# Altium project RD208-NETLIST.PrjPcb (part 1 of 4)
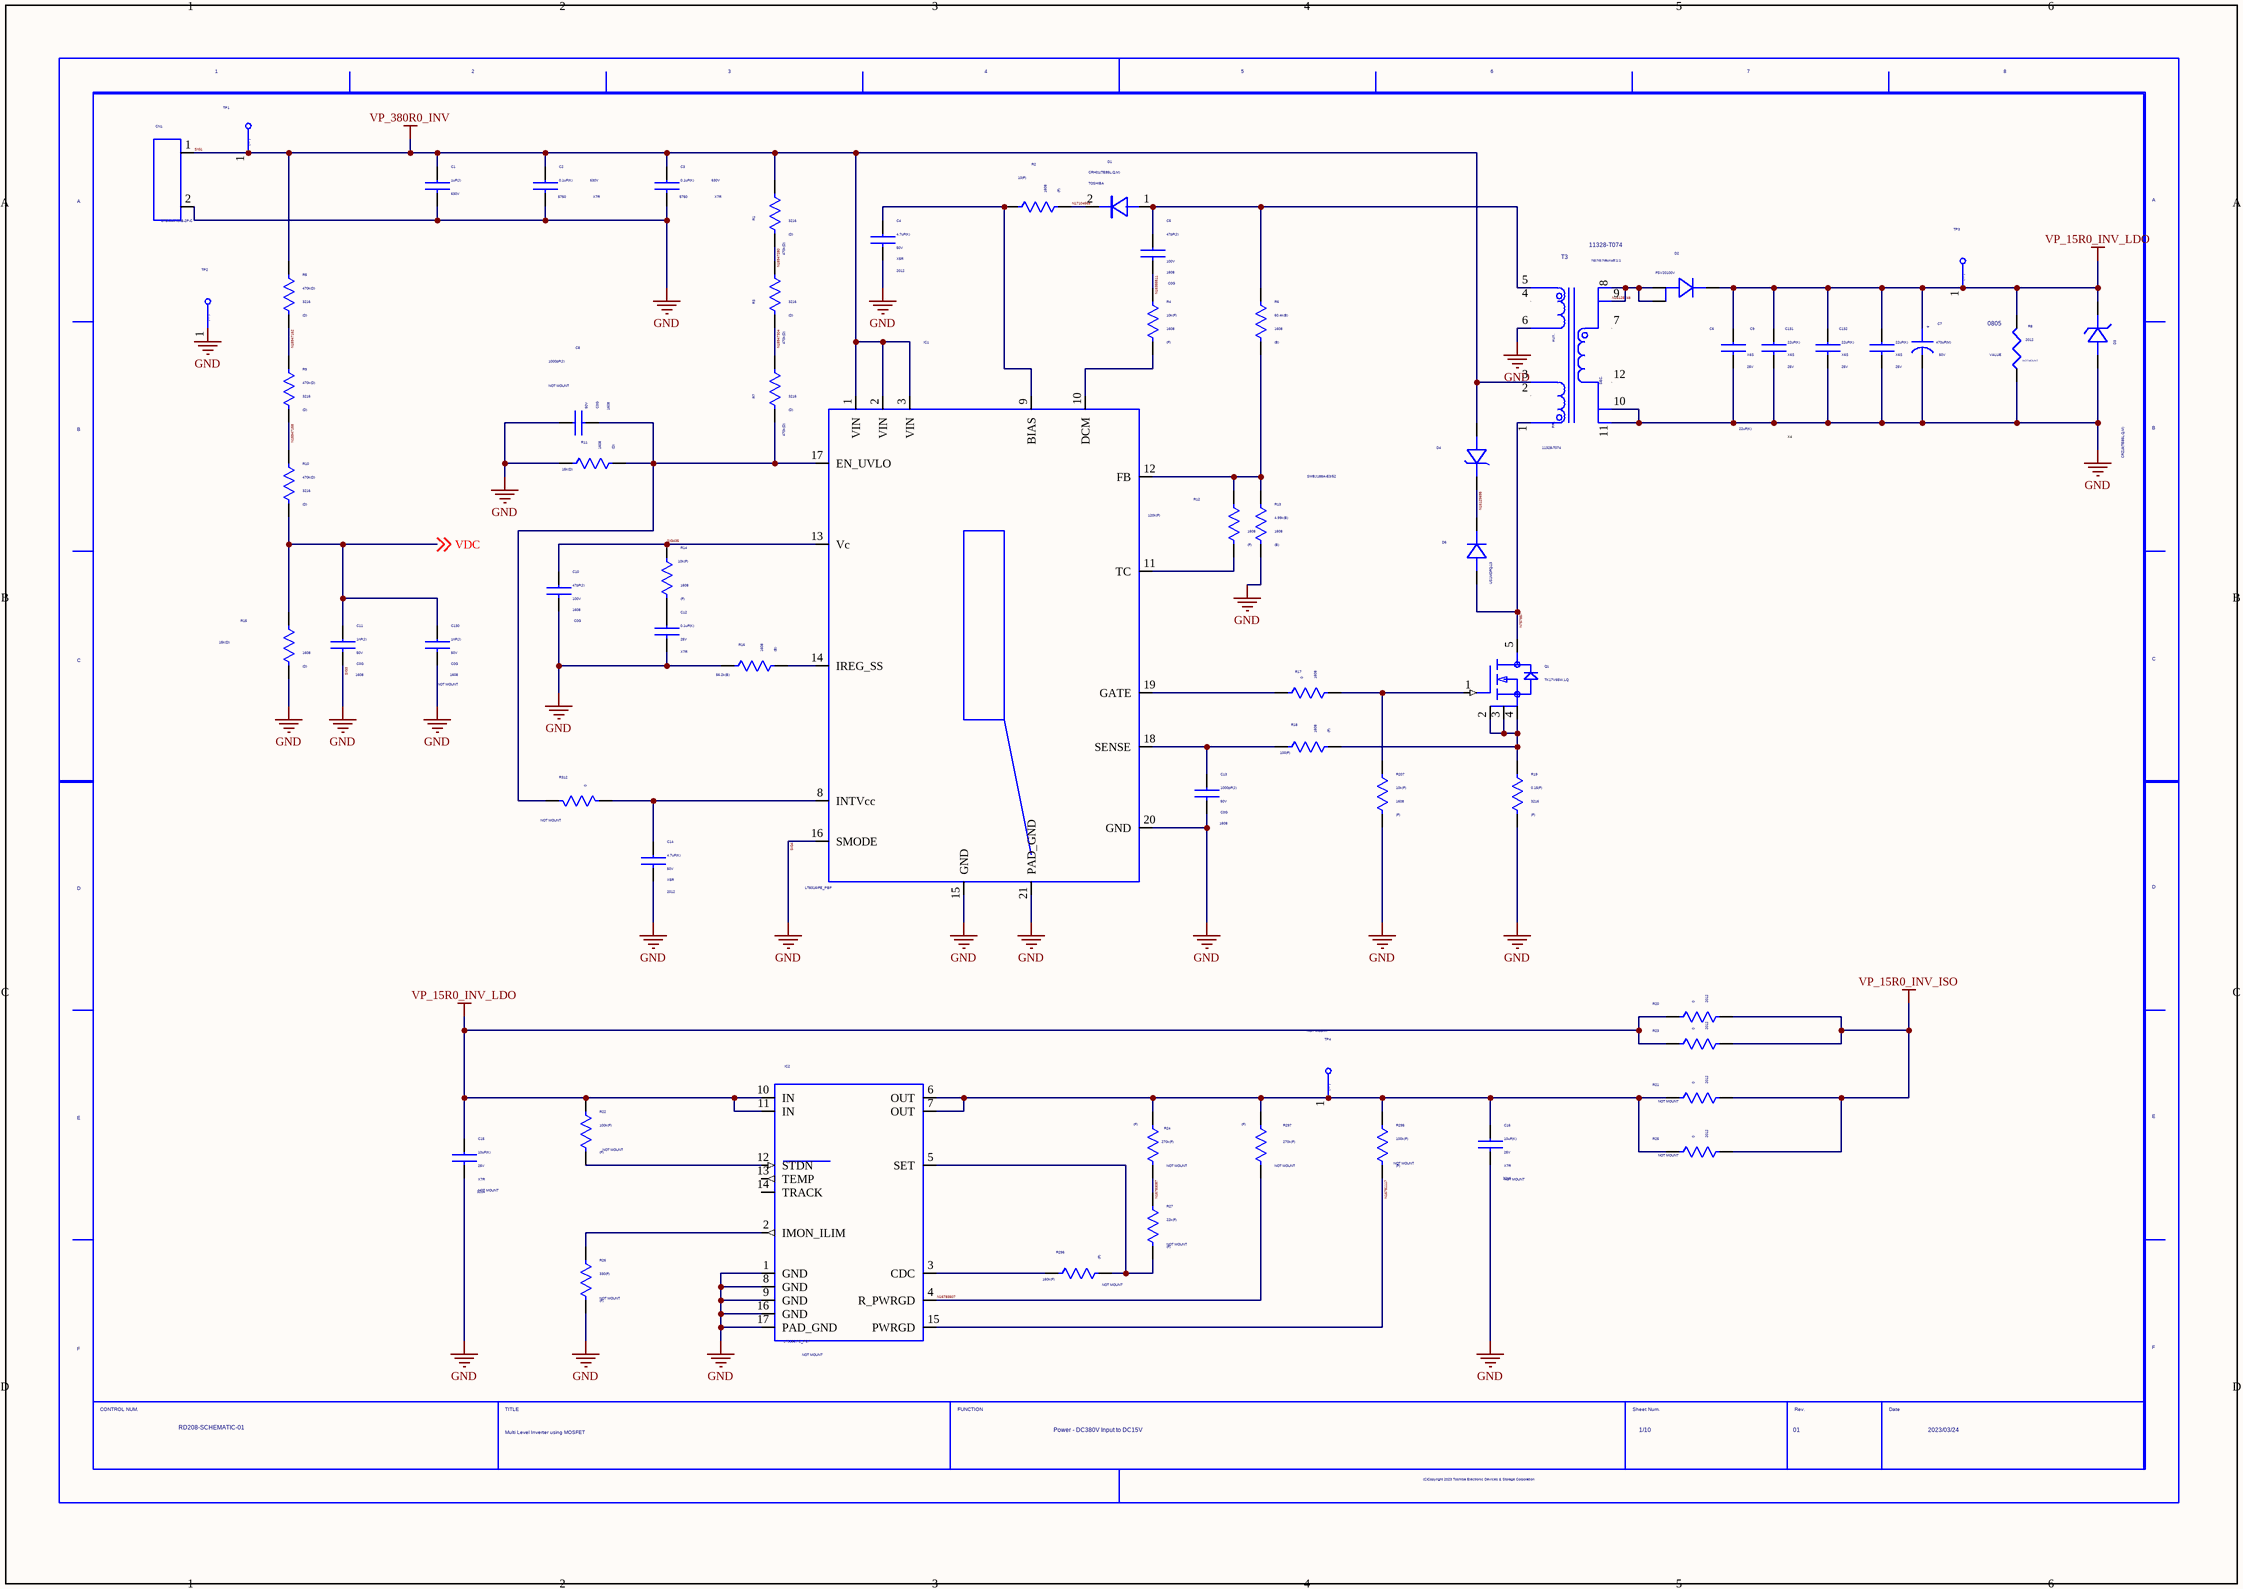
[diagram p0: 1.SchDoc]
10 sheets, 782 parts. Net scope: global (net labels, ports and power ports of the same name join across sheets).
Sheets:
  1.SchDoc
  2.SchDoc
  3.SchDoc
  4.SchDoc
  5.SchDoc
  6.SchDoc
  7.SchDoc
  8.SchDoc
  9.SchDoc
  10.SchDoc

## Sheet 1.SchDoc
size 420 x 297 mm

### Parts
(Parts that share a designator on the sheet are numbered #1, #2 ... from top to bottom, then left to right.)
C1  VAL2: 630V  VAL1: 1uF(J)  (hidden comment: ECWFG2J105P1)
C2  VAL2: 630V  SIZECODESMD: 5750  VALUE4: X7R  VAL1: 0.1uF(K)  (hidden comment: 2220CC104KAT1A)
C3  VAL2: 630V  SIZECODESMD: 5750  VALUE4: X7R  VAL1: 0.1uF(K)  (hidden comment: 2220CC104KAT1A)
C4  VAL2: 50V  SIZECODESMD: 2012  VALUE4: X5R  VAL1: 4.7uF(K)  (hidden comment: GRM21BR61H475KE51L)
C5  VAL2: 100V  SIZECODESMD: 1608  VALUE4: C0G  VAL1: 47pF(J)  (hidden comment: GRM1885C2A470JA01D)
C6  VAL2: 25V  VALUE4: X6S  VAL1: 22uF(K)  (hidden comment: GRM31CC81E226KE11L)
C7  VAL2: 50V  VAL1: 470uF(M)  (hidden comment: EKY_500ELL471ML15S)
C8  VAL2: 50V  SIZECODESMD: 1608  VALUE4: C0G  VAL1: 1000pF(J)  NOTMOUNT: NOT MOUNT  (hidden comment: GRM1885C1H102JA01J)
C9  VAL2: 25V  VALUE4: X6S  VAL1: 22uF(K)  (hidden comment: GRM31CC81E226KE11L)
C10  VAL2: 100V  SIZECODESMD: 1608  VALUE4: C0G  VAL1: 47pF(J)  (hidden comment: GRM1885C2A470JA01D)
C11  VAL2: 50V  SIZECODESMD: 1608  VALUE4: C0G  VAL1: 1nF(J)  (hidden comment: GRM1885C1H102JA01J)
C12  VAL2: 25V  VALUE4: X7R  VAL1: 0.1uF(K)  (hidden comment: GRM155R71E104KE14D)
C13  VAL2: 50V  SIZECODESMD: 1608  VALUE4: C0G  VAL1: 1000pF(J)  (hidden comment: GRM1885C1H102JA01J)
C14  VAL2: 50V  SIZECODESMD: 2012  VALUE4: X5R  VAL1: 4.7uF(K)  (hidden comment: GRM21BR61H475KE51L)
C15  VAL2: 25V  SIZECODESMD: 3216  VALUE4: X7R  VAL1: 10uF(K)  NOTMOUNT: NOT MOUNT  (hidden comment: GRM31CR71E106MA12K)
C16  VAL2: 25V  SIZECODESMD: 3216  VALUE4: X7R  VAL1: 10uF(K)  NOTMOUNT: NOT MOUNT  (hidden comment: GRM31CR71E106MA12K)
C130  VAL2: 50V  SIZECODESMD: 1608  VALUE4: C0G  VAL1: 1nF(J)  NOTMOUNT: NOT MOUNT  (hidden comment: GRM1885C1H102JA01J)
C131  VAL2: 25V  VALUE4: X6S  VAL1: 22uF(K)  (hidden comment: GRM31CC81E226KE11L)
C132  VAL2: 25V  VALUE4: X6S  VAL1: 22uF(K)  (hidden comment: GRM31CC81E226KE11L)
CN1  VAL1: OTB-640NS-B-2P-C  (hidden comment: OTB_640NS_B_2P_C)
D1  USERCOMPTEXT3: TOSHIBA  VAL3: CRH01(TE85L,Q,M)  (hidden comment: CRH01_TE85L,Q,M_)
D2  FSV20100V  [SOD-323]
D3  VAL3: CRZ18(TE85L,Q,M)  (hidden comment: CRZ18_TE85L,Q,M_)
D4  VAL1: SMBJ188A-E3/52  (hidden comment: SMBJ188A_E3_52)
D6  VAL1: US1MDFQ-13  (hidden comment: US1MDFQ_13)
IC1  LT8316IFE_PBF
IC2  NOTMOUNT: NOT MOUNT  (hidden comment: LT3086IFE_PBF)
Q1  TK17V65W,LQ
R1  SIZECODESMD: 3216  VALUE4: (D)  VAL1: 470k(D)  (hidden comment: HV73V2BTTD4703D)
R2  SIZECODESMD: 1608  VALUE4: (F)  VAL1: 10(F)  (hidden comment: ERJ3EKF10R0V)
R3  SIZECODESMD: 3216  VALUE4: (D)  VAL1: 470k(D)  (hidden comment: HV73V2BTTD4703D)
R4  SIZECODESMD: 1608  VALUE4: (F)  VAL1: 10k(F)  (hidden comment: ERJ3EKF1002V)
R5  SIZECODESMD: 3216  VALUE4: (D)  VAL1: 470k(D)  (hidden comment: HV73V2BTTD4703D)
R6  SIZECODESMD: 1608  VAL1: 60.4k(B)  VLUE4: (B)  (hidden comment: ERA3APB6042V)
R7  SIZECODESMD: 3216  VALUE4: (D)  VAL1: 470k(D)  (hidden comment: HV73V2BTTD4703D)
R8  SIZE: 0805  VAL1: VALUE  SIZECODESMD: 2012  NOTMOUNT: NOT MOUNT  [3216]  (hidden comment: AAC_0805)
R9  SIZECODESMD: 3216  VALUE4: (D)  VAL1: 470k(D)  (hidden comment: HV73V2BTTD4703D)
R10  SIZECODESMD: 3216  VALUE4: (D)  VAL1: 470k(D)  (hidden comment: HV73V2BTTD4703D)
R11  SIZECODESMD: 1608  VALUE4: (D)  VAL1: 15k(D)  (hidden comment: RK73H1JRTTD1502D)
R12  SIZECODESMD: 1608  VALUE4: (F)  VAL1: 120k(F)  (hidden comment: ERJ3EKF1203V)
R13  SIZECODESMD: 1608  VALUE4: (B)  VAL1: 4.99k(B)  (hidden comment: ERA3AEB4991V)
R14  SIZECODESMD: 1608  VALUE4: (F)  VAL1: 10k(F)  (hidden comment: ERJ3EKF1002V)
R15  SIZECODESMD: 1608  VALUE4: (D)  VAL1: 15k(D)  (hidden comment: RK73H1JRTTD1502D)
R16  SIZECODESMD: 1608  VALUE4: (B)  VAL1: 56.2k(B)  (hidden comment: ERA3ARB5622V)
R17  SIZECODESMD: 1608  VAL1: 0  (hidden comment: ERJ3GEY0R00V)
R18  SIZECODESMD: 1608  VALUE4: (F)  VAL1: 100(F)  (hidden comment: ERJ3EKF1000V)
R19  SIZECODESMD: 3216  VALUE4: (F)  VAL1: 0.15(F)  (hidden comment: KRL1632E_M_R150_F_T5)
R20  SIZECODESMD: 2012  VAL1: 0  (hidden comment: ERJ6GEY0R00V)
R21  SIZECODESMD: 2012  VAL1: 0  NOTMOUNT: NOT MOUNT  (hidden comment: ERJ6GEY0R00V)
R22  VALUE4: (F)  VAL1: 100k(F)  NOTMOUNT: NOT MOUNT  (hidden comment: ERJ2RKF1003X)
R23  SIZECODESMD: 2012  VAL1: 0  (hidden comment: ERJ6GEY0R00V)
R24  VALUE4: (F)  VAL1: 270k(F)  NOTMOUNT: NOT MOUNT  (hidden comment: ERJ2RKF2703X)
R25  SIZECODESMD: 2012  VAL1: 0  NOTMOUNT: NOT MOUNT  (hidden comment: ERJ6GEY0R00V)
R26  VALUE4: (F)  VAL1: 330(F)  NOTMOUNT: NOT MOUNT  (hidden comment: ERJ2RKF3300X)
R27  VALUE4: (F)  VAL1: 22k(F)  NOTMOUNT: NOT MOUNT  (hidden comment: ERJ2RKF2202X)
R207  SIZECODESMD: 1608  VALUE4: (F)  VAL1: 10k(F)  (hidden comment: ERJ3EKF1002V)
R295  VALUE4: (F)  VAL1: 100k(F)  NOTMOUNT: NOT MOUNT  (hidden comment: ERJ2RKF1003X)
R296  VALUE4: (F)  VAL1: 160k(F)  NOTMOUNT: NOT MOUNT  (hidden comment: ERJ2RKF1603X)
R297  VALUE4: (F)  VAL1: 270k(F)  NOTMOUNT: NOT MOUNT  (hidden comment: ERJ2RKF2703X)
R312  VAL1: 0  NOTMOUNT: NOT MOUNT  (hidden comment: ERJ2GE0R00X)
T3  VAL2: Np:Ns:Naux=8:1:1  VAL1: 11328-T074  (hidden comment: 11328_T074)
TP1  TP  (value not drawn)
TP2  TP  (value not drawn)
TP3  TP  (value not drawn)
TP4  NOTMOUNT: NOT MOUNT  (hidden comment: TP)
U?#1  DATE: 2023/03/24  TITLE: Multi Level Inverter using MOSFET  DRAWINGNUMBER: RD208-SCHEMATIC-01  REVISION: 01  SHEETNUMBER: 1/10  FUNCTION: Power - DC380V Input to DC15V  (hidden comment: WAKU_DEF100)

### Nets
GND: C1.2 C2.2 C3.2 C4.2 C6.2 C7.2 C8.1 C9.2 C10.2 C11.2 C12.2 C13.2 C14.2 C15.2 C16.2 C130.2 C131.2 C132.2 CN1.2 D3.A(ANODE) IC1.15(GND) IC1.16(SMODE) IC1.20(GND) IC1.21(PAD_GND) IC2.1(GND) IC2.8(GND) IC2.9(GND) IC2.16(GND) IC2.17(PAD_GND) R8.1 R11.1 R13.2 R15.2 R16.1 R19.2 R26.2 R207.2 T3.6 T3.10 T3.11 TP2.1  [also labelled SIG3, SIG4]  [project net SIG200]
SIG1: C1.1 C2.1 C3.1 CN1.1 D4.A(ANODE) IC1.1(VIN) IC1.2(VIN) IC1.3(VIN) R1.1 R5.1 T3.3 TP1.1  [also labelled VP_380R0_INV]
VP_15R0_INV_ISO: R20.2 R21.2 R23.2 R25.2
VP_15R0_INV_LDO: C6.1 C7.1 C9.1 C15.1 C131.1 C132.1 D2.3(CATHODE) D3.K(CATHODE) IC2.10(IN) IC2.11(IN) R8.2 R20.1 R22.1 R23.1 TP3.1
LDO_15V_CDC: IC2.3(CDC) R296.1
LDO_15V_ILIM: IC2.2(IMON_ILIM) R26.1
LDO_15V_SET: IC2.5(SET) R27.2 R296.2
LDO_15V_STD_N: IC2.12(STDN) R22.2
LDO_15VOUT: C16.1 IC2.6(OUT) IC2.7(OUT) R21.1 R24.2 R25.1 R295.1 R297.2 TP4.1
LT8316_BIAS: C4.1 IC1.9(BIAS) R2.1
LT8316_DCM: IC1.10(DCM) R4.2
LT8316_EN: C8.2 IC1.17(EN_UVLO) R7.2 R11.2 R312.2
LT8316_FB: IC1.12(FB) R6.2 R12.1 R13.1
LT8316_FB_B: C5.1 D1.1(A) R6.1 T3.5
LT8316_GATE: IC1.19(GATE) R17.1
LT8316_GATE_B: Q1.1(G) R17.2 R207.1
LT8316_INTVCC: C14.1 IC1.8(INTVcc) R312.1
LT8316_IREG: IC1.14(IREG_SS) R16.2
LT8316_SENSE: C13.1 IC1.18(SENSE) R18.1
LT8316_SENSE_B: Q1.2(S2) Q1.3(S3) Q1.4(S4) R18.2 R19.1
LT8316_TC: IC1.11(TC) R12.2
N757857: D6.A(ANODE) Q1.5(D) T3.1
N15947158: R9.2 R10.1
N15947162: R5.2 R9.1
N15947280: R1.2 R3.1
N15947304: R3.2 R7.1
N16128748: D2.1(ANODE-1) D2.2(ANODE-2) T3.8 T3.9
N16129695: D4.K(CATHODE) D6.K(CATHODE)
N16355511: C5.2 R4.1
N16781117: IC2.15(PWRGD) R295.2
N16783087: R24.1 R27.1
N16783507: IC2.4(R_PWRGD) R297.1
N17104568: D1.2(C) R2.2
SIG435: C10.1 IC1.13(Vc) R14.1
VDC: C11.1 C130.1 R10.2 R15.1 ; off-sheet VDC
NetC12_1: C12.1 R14.2

Not connected (* = marked no-connect by the designer): IC2 13(TEMP) 14(TRACK); T3 2 4 7 12

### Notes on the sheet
- X4

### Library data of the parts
C1 = ECWFG2J105P1: MANUFACTURER: PANASONIC; ITEM: CAP Film; TIME: 08:44:47; UPDATEUSER: t5459927; SAVECOUNT: 1; OriginalSymbolOrigin: (0,0); INSTANCENAME: INS15925304
C2 = 2220CC104KAT1A: MANUFACTURER: AVX; ITEM: CAP Ceramic; TIME: 08:44:47; UPDATEUSER: t5459927; SAVECOUNT: 1; OriginalSymbolOrigin: (0,0); INSTANCENAME: INS16805650
C3 = 2220CC104KAT1A: MANUFACTURER: AVX; ITEM: CAP Ceramic; TIME: 08:44:47; UPDATEUSER: t5459927; SAVECOUNT: 1; OriginalSymbolOrigin: (0,0); INSTANCENAME: INS16806135
C4 = GRM21BR61H475KE51L: MANUFACTURER: MURATA; ITEM: CAP Ceramic; TIME: 08:44:46; UPDATEUSER: t5459927; SAVECOUNT: 1; OriginalSymbolOrigin: (0,0); INSTANCENAME: INS15926838
C5 = GRM1885C2A470JA01D: MANUFACTURER: MURATA; ITEM: CAP Ceramic; TIME: 08:44:47; UPDATEUSER: t5459927; SAVECOUNT: 1; OriginalSymbolOrigin: (0,0); INSTANCENAME: INS15927173
C6 = GRM31CC81E226KE11L: MANUFACTURER: MURATA; ITEM: CAP Ceramic; SIZECODESMD: 3216; TIME: 08:44:47; UPDATEUSER: t5459927; SAVECOUNT: 1; OriginalSymbolOrigin: (0,0); INSTANCENAME: INS16787498
C7 = EKY_500ELL471ML15S: MANUFACTURER: Nippon Chemi-Con; ITEM: CAP ALUM; SIZECODESMD: 16.0mm; COMP: EKY-500ELL471ML15S; TIME: 08:44:47; UPDATEUSER: t5459927; SAVECOUNT: 1; OriginalSymbolOrigin: (0,2540); INSTANCENAME: INS15936364
C8 = GRM1885C1H102JA01J: MANUFACTURER: MURATA; ITEM: CAP Ceramic; TIME: 08:44:47; UPDATEUSER: t5459927; SAVECOUNT: 1; OriginalSymbolOrigin: (0,0); INSTANCENAME: INS16256315
C9 = GRM31CC81E226KE11L: MANUFACTURER: MURATA; ITEM: CAP Ceramic; SIZECODESMD: 3216; TIME: 08:44:47; UPDATEUSER: t5459927; SAVECOUNT: 1; OriginalSymbolOrigin: (0,0); INSTANCENAME: INS16787510
C10 = GRM1885C2A470JA01D: MANUFACTURER: MURATA; ITEM: CAP Ceramic; TIME: 08:44:47; UPDATEUSER: t5459927; SAVECOUNT: 1; OriginalSymbolOrigin: (0,0); INSTANCENAME: INS15928528
C11 = GRM1885C1H102JA01J: MANUFACTURER: MURATA; ITEM: CAP Ceramic; TIME: 08:44:47; UPDATEUSER: t5459927; SAVECOUNT: 1; OriginalSymbolOrigin: (0,0); INSTANCENAME: INS16143125
C12 = GRM155R71E104KE14D: MANUFACTURER: MURATA; ITEM: CAP Ceramic; SIZECODESMD: 1005; TIME: 08:44:45; UPDATEUSER: t5459927; SAVECOUNT: 1; OriginalSymbolOrigin: (0,0); INSTANCENAME: INS15928810
C13 = GRM1885C1H102JA01J: MANUFACTURER: MURATA; ITEM: CAP Ceramic; TIME: 08:44:47; UPDATEUSER: t5459927; SAVECOUNT: 1; OriginalSymbolOrigin: (0,0); INSTANCENAME: INS15928036
C14 = GRM21BR61H475KE51L: MANUFACTURER: MURATA; ITEM: CAP Ceramic; TIME: 08:44:46; UPDATEUSER: t5459927; SAVECOUNT: 1; OriginalSymbolOrigin: (0,0); INSTANCENAME: INS15928288
C15 = GRM31CR71E106MA12K: MANUFACTURER: MURATA; ITEM: CAP Ceramic; TIME: 08:44:46; UPDATEUSER: t5459927; SAVECOUNT: 1; OriginalSymbolOrigin: (0,0); INSTANCENAME: INS3166104
C16 = GRM31CR71E106MA12K: MANUFACTURER: MURATA; ITEM: CAP Ceramic; TIME: 08:44:46; UPDATEUSER: t5459927; SAVECOUNT: 1; OriginalSymbolOrigin: (0,0); INSTANCENAME: INS3166501
C130 = GRM1885C1H102JA01J: MANUFACTURER: MURATA; ITEM: CAP Ceramic; TIME: 08:44:47; UPDATEUSER: t5459927; SAVECOUNT: 1; OriginalSymbolOrigin: (0,0); INSTANCENAME: INS16143791
C131 = GRM31CC81E226KE11L: MANUFACTURER: MURATA; ITEM: CAP Ceramic; SIZECODESMD: 3216; TIME: 08:44:47; UPDATEUSER: t5459927; SAVECOUNT: 1; OriginalSymbolOrigin: (0,0); INSTANCENAME: INS16787460
C132 = GRM31CC81E226KE11L: MANUFACTURER: MURATA; ITEM: CAP Ceramic; SIZECODESMD: 3216; TIME: 08:44:47; UPDATEUSER: t5459927; SAVECOUNT: 1; OriginalSymbolOrigin: (0,0); INSTANCENAME: INS16787472
CN1 = OTB_640NS_B_2P_C: MANUFACTURER: OSADA; ITEM: Connector; VAL2: 11mm   x2; TIME: 08:44:47; UPDATEUSER: t5459927; SAVECOUNT: 1; SAVEAREA0: -10166,-15544,12232,852; OriginalSymbolOrigin: (0,0); INSTANCENAME: INS17151887
D1 = CRH01_TE85L,Q,M_: 5TH PART FIELD: CRH01; ITEM: DIODE; COMP: CRH01-12; TIME: 08:44:47; UPDATEUSER: t5459927; SAVECOUNT: 1; OriginalSymbolOrigin: (0,0); INSTANCENAME: INS760252
D2 = FSV20100V: MANUFACTURER: On semiconductor; COMP: FSV20100V-123; ITEM: DIODE; TIME: 08:44:47; UPDATEUSER: t5459927; SAVECOUNT: 1; OriginalSymbolOrigin: (0,2540); INSTANCENAME: INS15937116
D3 = CRZ18_TE85L,Q,M_: MANUFACTURER: TOSHIBA; COMP: CRZ18; ITEM: DIODE Zener; TIME: 08:44:47; UPDATEUSER: t5459927; SAVECOUNT: 1; OriginalSymbolOrigin: (0,0); INSTANCENAME: INS16129113
D4 = SMBJ188A_E3_52: MANUFACTURER: Vishay; COMP: SMBJ188A-E3_52; ITEM: DIODE TVS; TIME: 08:44:47; UPDATEUSER: t5459927; SAVECOUNT: 1; OriginalSymbolOrigin: (0,0); INSTANCENAME: INS15937273
D6 = US1MDFQ_13: MANUFACTURER: DIODES; ITEM: DIODE; VAL2: 1000V; SIZECODESMD: 1A; TIME: 08:44:47; UPDATEUSER: t5459927; SAVECOUNT: 1; OriginalSymbolOrigin: (0,0); INSTANCENAME: INS16150519
IC1 = LT8316IFE_PBF: MANUFACTURER: Analog Devices; ITEM: IC DCDC; TIME: 08:44:47; UPDATEUSER: PS4_common_PC; UPDATETIME: 14:20:20; SAVECOUNT: 5; SAVEAREA0: -89670,-104109,148818,4559; OriginalSymbolOrigin: (0,0); COMP: LT-20-Lead-Plastic-TSSOP-FE-R-SP-17p
IC2 = LT3086IFE_PBF: MANUFACTURER: Analog Devices; ITEM: LDO; TIME: 08:44:47; UPDATEUSER: PS4_common_PC; UPDATETIME: 14:21:05; SAVECOUNT: 5; SAVEAREA0: -46534,-51518,75335,4012; OriginalSymbolOrigin: (0,0)
Q1 = TK17V65W,LQ: MANUFATURER: TOSHIBA; ITEM: FET; TIME: 08:44:45; UPDATEUSER: t5459927; SAVECOUNT: 1; OriginalSymbolOrigin: (0,0); INSTANCENAME: INS15937568
R1 = HV73V2BTTD4703D: MANUFACTURER: KOA; ITEM: Register; VAL2: 0.33W; TIME: 08:44:45; UPDATEUSER: t5459927; SAVECOUNT: 1; OriginalSymbolOrigin: (0,0); INSTANCENAME: INS16809998
R2 = ERJ3EKF10R0V: MANUFACTURER: Panasonic; ITEM: Register; VAL2: 100mW; TIME: 08:44:45; UPDATEUSER: t5459927; SAVECOUNT: 1; OriginalSymbolOrigin: (0,0); INSTANCENAME: INS17104536
R3 = HV73V2BTTD4703D: MANUFACTURER: KOA; ITEM: Register; VAL2: 0.33W; TIME: 08:44:45; UPDATEUSER: t5459927; SAVECOUNT: 1; OriginalSymbolOrigin: (0,0); INSTANCENAME: INS16810014
R4 = ERJ3EKF1002V: MANUFACTURER: Panasonic; ITEM: Register; VAL2: 100mW; TIME: 08:44:46; UPDATEUSER: t5459927; SAVECOUNT: 1; OriginalSymbolOrigin: (0,0); INSTANCENAME: INS15927083
R5 = HV73V2BTTD4703D: MANUFACTURER: KOA; ITEM: Register; VAL2: 0.33W; TIME: 08:44:45; UPDATEUSER: t5459927; SAVECOUNT: 1; OriginalSymbolOrigin: (0,0); INSTANCENAME: INS16806683
R6 = ERA3APB6042V: MANUFACTURER: Panasonic; ITEM: Register; VAL2: 100mW; TIME: 08:44:47; UPDATEUSER: t5459927; SAVECOUNT: 1; OriginalSymbolOrigin: (0,0); INSTANCENAME: INS15927417
R7 = HV73V2BTTD4703D: MANUFACTURER: KOA; ITEM: Register; VAL2: 0.33W; TIME: 08:44:45; UPDATEUSER: t5459927; SAVECOUNT: 1; OriginalSymbolOrigin: (0,0); INSTANCENAME: INS16810030
R8 = AAC_0805: RES.,OPT,1206; 7TH PART FIELD: RES.,; 4TH PART FIELD: VISHAY,; 3RD PART FIELD: CHIP; 2ND PART FIELD: 1-5%; 5TH PART FIELD: CRCW0805---RT6; 1ST PART FIELD: 1/8W; TIME: 08:44:45; UPDATEUSER: t5459927; SAVECOUNT: 1; OriginalSymbolOrigin: (0,0); INSTANCENAME: INS757555
R9 = HV73V2BTTD4703D: MANUFACTURER: KOA; ITEM: Register; VAL2: 0.33W; TIME: 08:44:45; UPDATEUSER: t5459927; SAVECOUNT: 1; OriginalSymbolOrigin: (0,0); INSTANCENAME: INS16806699
R10 = HV73V2BTTD4703D: MANUFACTURER: KOA; ITEM: Register; VAL2: 0.33W; TIME: 08:44:45; UPDATEUSER: t5459927; SAVECOUNT: 1; OriginalSymbolOrigin: (0,0); INSTANCENAME: INS16806715
R11 = RK73H1JRTTD1502D: MANUFACTURER: KOA; ITEM: Register; VAL2: 100mW; TIME: 08:44:47; UPDATEUSER: t5459927; SAVECOUNT: 1; OriginalSymbolOrigin: (0,0); INSTANCENAME: INS16809511
R12 = ERJ3EKF1203V: MANUFACTURER: Panasonic; ITEM: Register; VAL2: 100mW; TIME: 08:44:47; UPDATEUSER: t5459927; SAVECOUNT: 1; OriginalSymbolOrigin: (0,0); INSTANCENAME: INS15927358
R13 = ERA3AEB4991V: MANUFACTURER: Panasonic; ITEM: Register; VAL2: 100mW; TIME: 08:44:47; UPDATEUSER: t5459927; SAVECOUNT: 1; OriginalSymbolOrigin: (0,0); INSTANCENAME: INS15927488
R14 = ERJ3EKF1002V: MANUFACTURER: Panasonic; ITEM: Register; VAL2: 100mW; TIME: 08:44:46; UPDATEUSER: t5459927; SAVECOUNT: 1; OriginalSymbolOrigin: (0,0); INSTANCENAME: INS15928669
R15 = RK73H1JRTTD1502D: MANUFACTURER: KOA; ITEM: Register; VAL2: 100mW; TIME: 08:44:47; UPDATEUSER: t5459927; SAVECOUNT: 1; OriginalSymbolOrigin: (0,0); INSTANCENAME: INS16808336
R16 = ERA3ARB5622V: MANUFACTURER: Panasonic; ITEM: Register; VAL2: 100mW; TIME: 08:44:47; UPDATEUSER: t5459927; SAVECOUNT: 1; OriginalSymbolOrigin: (0,0); INSTANCENAME: INS15929035
R17 = ERJ3GEY0R00V: MANUFACTURER: Panasonic; ITEM: Register; VAL2: 1/10W; TIME: 08:44:45; UPDATEUSER: t5459927; SAVECOUNT: 1; OriginalSymbolOrigin: (0,0); INSTANCENAME: INS16641918
R18 = ERJ3EKF1000V: MANUFACTURER: Panasonic; ITEM: Register; VAL2: 100mW; TIME: 08:44:47; UPDATEUSER: t5459927; SAVECOUNT: 1; OriginalSymbolOrigin: (0,0); INSTANCENAME: INS15927883
R19 = KRL1632E_M_R150_F_T5: MANUFACTURER: Susumu; ITEM: Register; VAL2: 750mW; COMP: KRL1632E-M-R150-F-T5; TIME: 08:44:47; UPDATEUSER: t5459927; SAVECOUNT: 1; OriginalSymbolOrigin: (0,0); INSTANCENAME: INS16131577
R20 = ERJ6GEY0R00V: MANUFACTURER: Panasonic; ITEM: Register; VAL2: 1/10W; TIME: 08:44:47; UPDATEUSER: t5459927; SAVECOUNT: 1; OriginalSymbolOrigin: (0,0); INSTANCENAME: INS16037390
R21 R25 = ERJ6GEY0R00V: MANUFACTURER: Panasonic; ITEM: Register; VAL2: 1/10W; TIME: 08:44:47; UPDATEUSER: t5459927; SAVECOUNT: 1; OriginalSymbolOrigin: (0,0); INSTANCENAME: INS16037454
R22 = ERJ2RKF1003X: MANUFACTURER: Panasonic; ITEM: Register; VAL2: 100mW; SIZECODESMD: 1005; TIME: 08:44:47; UPDATEUSER: t5459927; SAVECOUNT: 1; OriginalSymbolOrigin: (0,0); INSTANCENAME: INS16779945
R23 = ERJ6GEY0R00V: MANUFACTURER: Panasonic; ITEM: Register; VAL2: 1/10W; TIME: 08:44:47; UPDATEUSER: t5459927; SAVECOUNT: 1; OriginalSymbolOrigin: (0,0); INSTANCENAME: INS16037422
R24 = ERJ2RKF2703X: MANUFACTURER: Panasonic; ITEM: Register; VAL2: 100mW; SIZECODESMD: 1005; TIME: 08:44:47; UPDATEUSER: t5459927; SAVECOUNT: 1; OriginalSymbolOrigin: (0,0); INSTANCENAME: INS16784959
R26 = ERJ2RKF3300X: MANUFACTURER: Panasonic; ITEM: Register; VAL2: 100mW; SIZECODESMD: 1005; TIME: 08:44:47; UPDATEUSER: t5459927; SAVECOUNT: 1; OriginalSymbolOrigin: (0,0); INSTANCENAME: INS16781755
R27 = ERJ2RKF2202X: MANUFACTURER: Panasonic; ITEM: Register; VAL2: 100mW; SIZECODESMD: 1005; TIME: 08:44:47; UPDATEUSER: t5459927; SAVECOUNT: 1; OriginalSymbolOrigin: (0,0); INSTANCENAME: INS16785023
R207 = ERJ3EKF1002V: MANUFACTURER: Panasonic; ITEM: Register; VAL2: 100mW; TIME: 08:44:46; UPDATEUSER: t5459927; SAVECOUNT: 1; OriginalSymbolOrigin: (0,0); INSTANCENAME: INS16642870
R295 = ERJ2RKF1003X: MANUFACTURER: Panasonic; ITEM: Register; VAL2: 100mW; SIZECODESMD: 1005; TIME: 08:44:47; UPDATEUSER: t5459927; SAVECOUNT: 1; OriginalSymbolOrigin: (0,0); INSTANCENAME: INS16779929
R296 = ERJ2RKF1603X: MANUFACTURER: Panasonic; ITEM: Register; VAL2: 100mW; SIZECODESMD: 1005; TIME: 08:44:47; UPDATEUSER: t5459927; SAVECOUNT: 1; OriginalSymbolOrigin: (0,0); INSTANCENAME: INS16782609
R297 = ERJ2RKF2703X: MANUFACTURER: Panasonic; ITEM: Register; VAL2: 100mW; SIZECODESMD: 1005; TIME: 08:44:47; UPDATEUSER: t5459927; SAVECOUNT: 1; OriginalSymbolOrigin: (0,0); INSTANCENAME: INS16783015
R312 = ERJ2GE0R00X: MANUFACTURER: Panasonic; ITEM: Register; VAL2: 1/10W; SIZECODESMD: 1005; TIME: 08:44:45; UPDATEUSER: t5459927; SAVECOUNT: 1; OriginalSymbolOrigin: (0,0); INSTANCENAME: INS17205038
T3 = 11328_T074: MANUFACTURER: SUMIDA; ITEM: Transformer; TIME: 08:44:47; UPDATEUSER: PS4_common_PC; UPDATETIME: 15:04:11; SAVECOUNT: 3; SAVEAREA0: -40366,-32840,49907,8293; OriginalSymbolOrigin: (-2540,2540)
TP1-TP4 = TP: TIME: 16:12:21; UPDATEUSER: fukuda-y; UPDATETIME: 16:18:11; SAVECOUNT: 2; SAVEAREA0: -242,-92,12810,7836; OriginalSymbolOrigin: (0,7620); VAL3: TH Hole dia. 1.0; COMP: TP-TH1.0-L1.6
U?#1 = WAKU_DEF100: PLOTTIME: HH:MM; SAVEAREA0: 185750,-43960,448537,75779; TIME: 14:30:25; UPDATEUSER: PS4_common_PC; UPDATETIME: 08:22:28; SAVECOUNT: 8; OriginalSymbolOrigin: (10160,284480)

## Sheet 2.SchDoc
size 420 x 297 mm
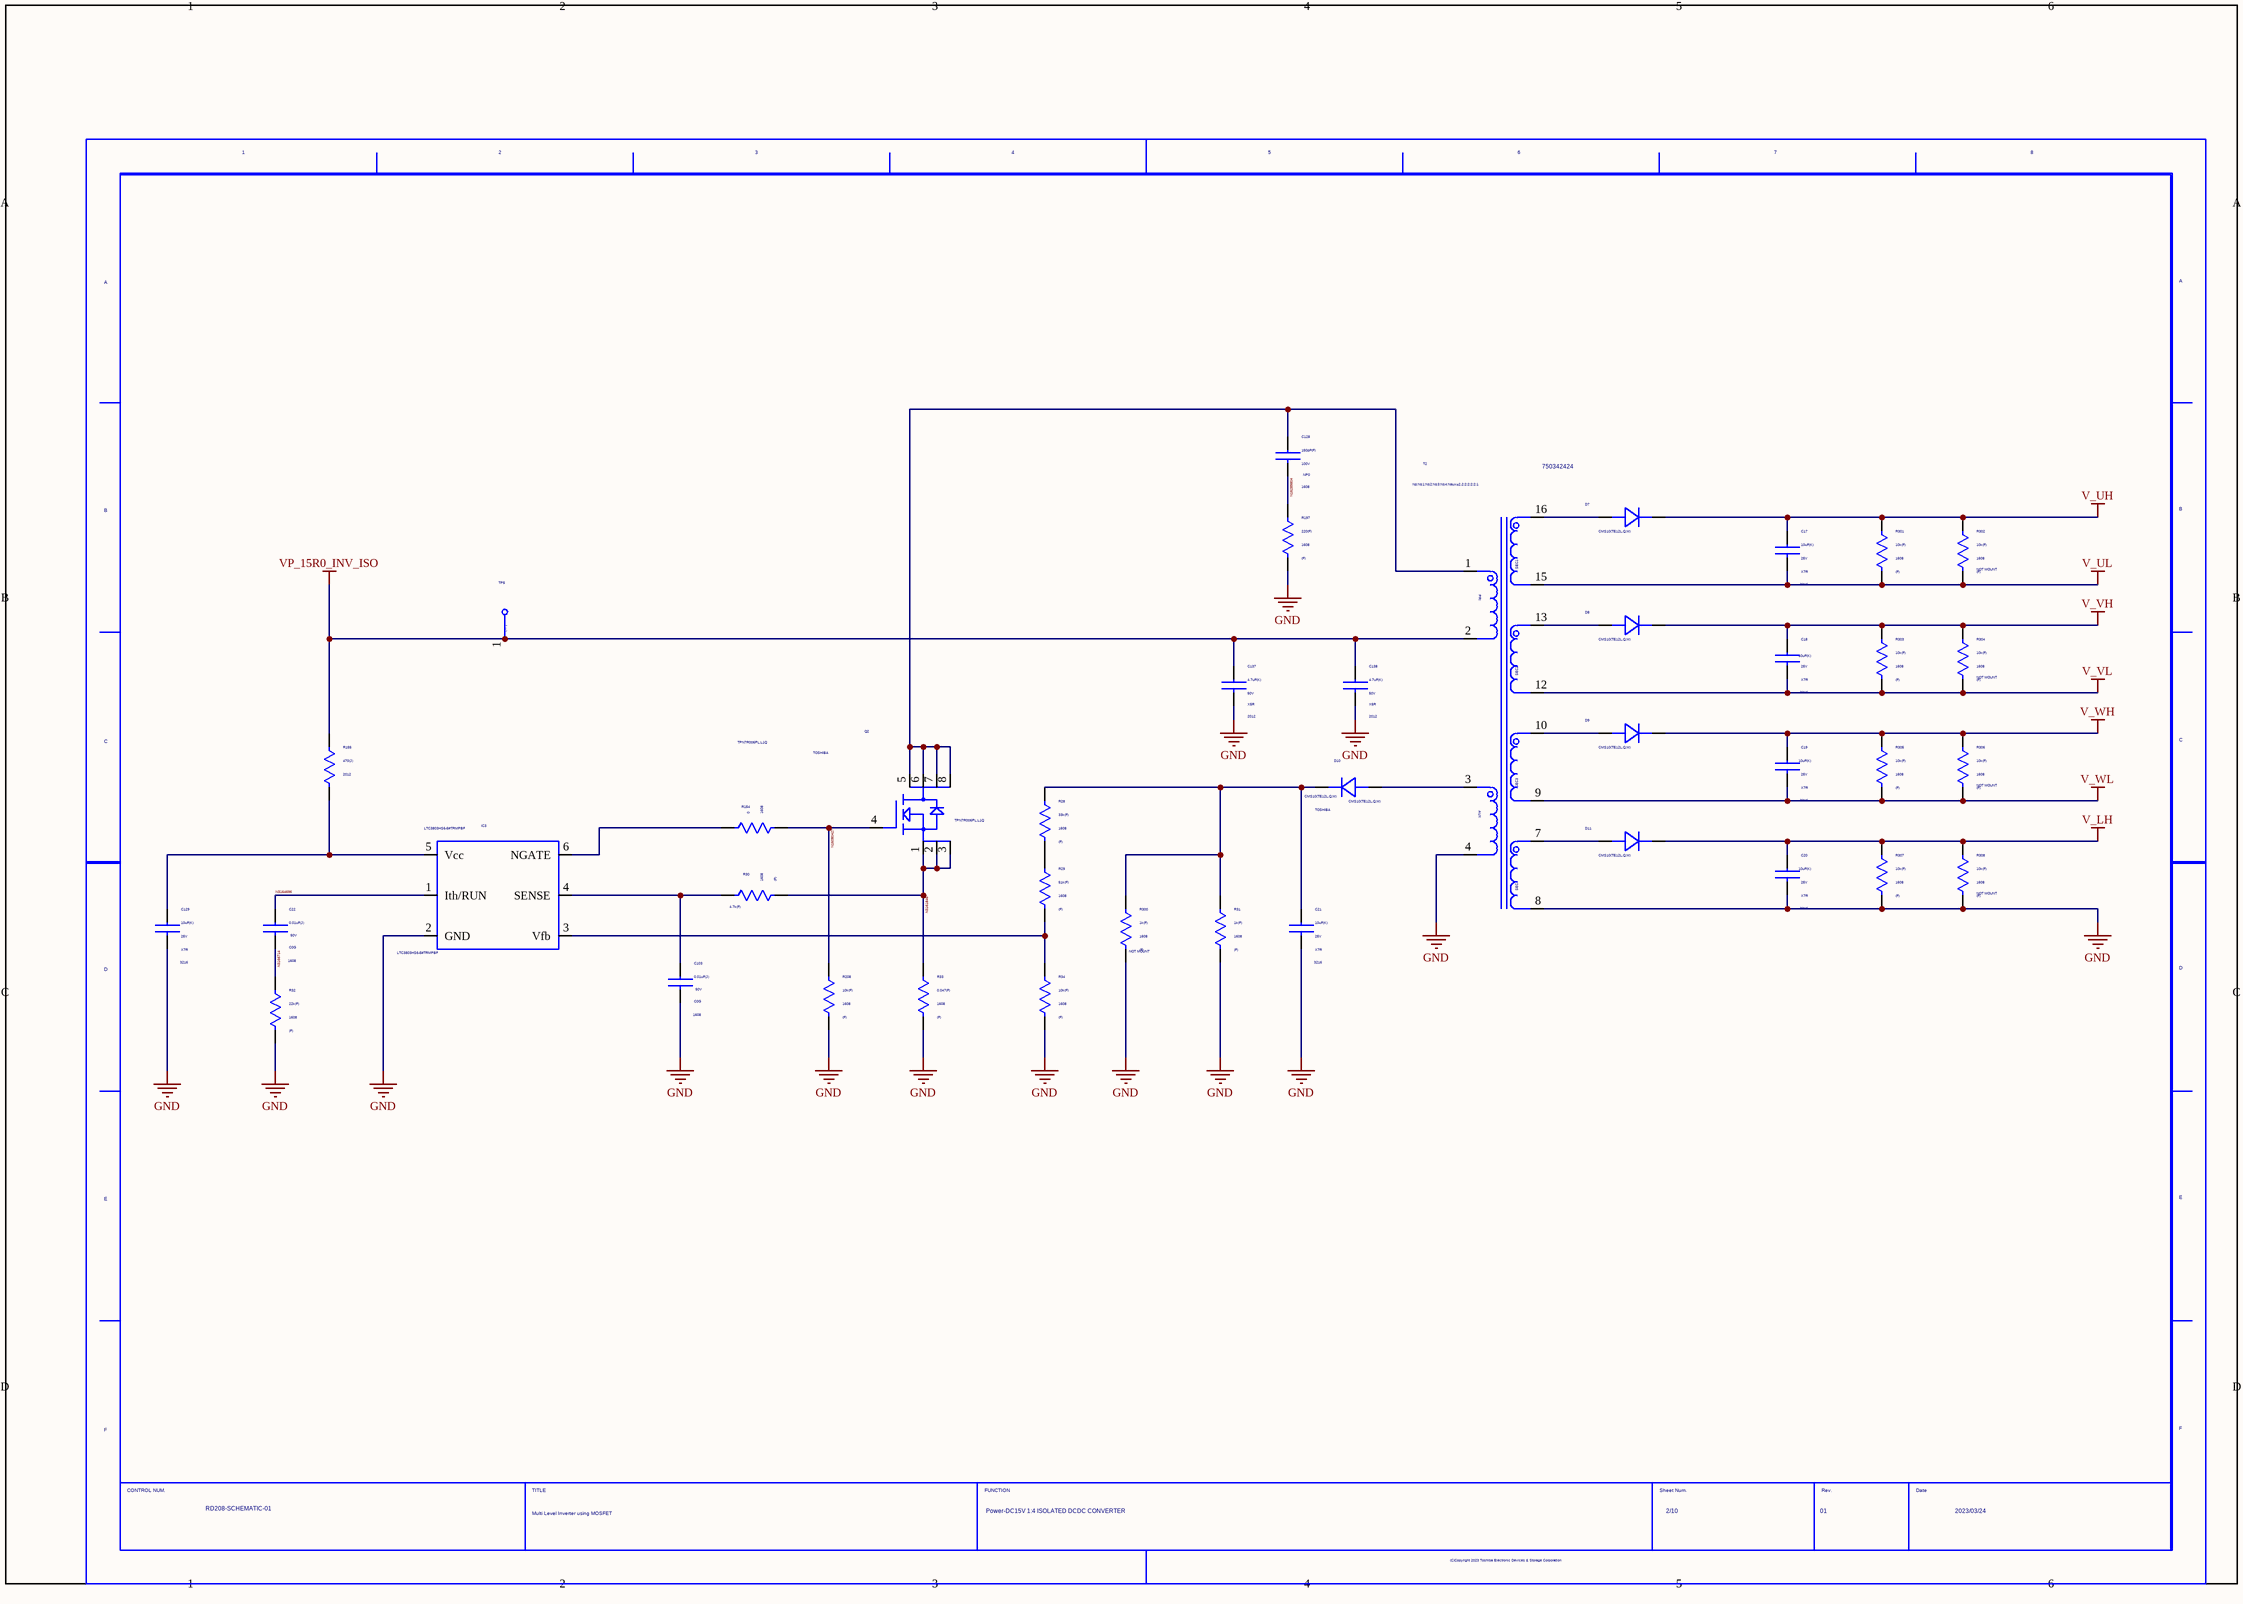
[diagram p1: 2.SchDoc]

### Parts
(Parts that share a designator on the sheet are numbered #1, #2 ... from top to bottom, then left to right.)
C17  VAL2: 25V  SIZECODESMD: 3216  VALUE4: X7R  VAL1: 10uF(K)  (hidden comment: GRM31CR71E106MA12K)
C18  VAL2: 25V  SIZECODESMD: 3216  VALUE4: X7R  VAL1: 10uF(K)  (hidden comment: GRM31CR71E106MA12K)
C19  VAL2: 25V  SIZECODESMD: 3216  VALUE4: X7R  VAL1: 10uF(K)  (hidden comment: GRM31CR71E106MA12K)
C20  VAL2: 25V  SIZECODESMD: 3216  VALUE4: X7R  VAL1: 10uF(K)  (hidden comment: GRM31CR71E106MA12K)
C21  VAL2: 25V  SIZECODESMD: 3216  VALUE4: X7R  VAL1: 10uF(K)  (hidden comment: GRM31CR71E106MA12K)
C22  VAL2: 50V  SIZECODESMD: 1608  VALUE4: C0G  VAL1: 0.01uF(J)  (hidden comment: GRM1885C1H103JA01J)
C103  VAL2: 50V  SIZECODESMD: 1608  VALUE4: C0G  VAL1: 0.01uF(J)  (hidden comment: GRM1885C1H103JA01J)
C128  VAL2: 100V  SIZECODESMD: 1608  VALUE4: NP0  VAL1: 150pF(F)  (hidden comment: 06031A151FAT2A)
C129  VAL2: 25V  SIZECODESMD: 3216  VALUE4: X7R  VAL1: 10uF(K)  (hidden comment: GRM31CR71E106MA12K)
C137  VAL2: 50V  SIZECODESMD: 2012  VALUE4: X5R  VAL1: 4.7uF(K)  (hidden comment: GRM21BR61H475KE51L)
C138  VAL2: 50V  SIZECODESMD: 2012  VALUE4: X5R  VAL1: 4.7uF(K)  (hidden comment: GRM21BR61H475KE51L)
D7  VAL1: CMS10(TE12L,Q,M)  (hidden comment: CMS10_TE12L,Q,M_)
D8  VAL1: CMS10(TE12L,Q,M)  (hidden comment: CMS10_TE12L,Q,M_)
D9  VAL1: CMS10(TE12L,Q,M)  (hidden comment: CMS10_TE12L,Q,M_)
D10  VAL1: CMS10(TE12L,Q,M)  USERCOMPTEXT3: TOSHIBA  (hidden comment: CMS10_TE12L,Q,M_)
D11  VAL1: CMS10(TE12L,Q,M)  (hidden comment: CMS10_TE12L,Q,M_)
IC3  VAL1: LTC3803HS6-5#TRMPBF  (hidden comment: LTC3803HS6_5#TRMPBF)
Q2  USERCOMPTEXT3: TOSHIBA  (hidden comment: TPN7R006PL,L1Q)
R28  SIZECODESMD: 1608  VALUE4: (F)  VAL1: 33k(F)  (hidden comment: ERJ3EKF3302V)
R29  SIZECODESMD: 1608  VALUE4: (F)  VAL1: 51k(F)  (hidden comment: ERJ3EKF5102V)
R30  SIZECODESMD: 1608  VALUE4: (F)  VAL1: 4.7k(F)  (hidden comment: ERJ3EKF4701V)
R31  SIZECODESMD: 1608  VALUE4: (F)  VAL1: 1k(F)  (hidden comment: ERJ3EKF1001V)
R32  SIZECODESMD: 1608  VALUE4: (F)  VAL1: 22k(F)  (hidden comment: ERJ3EKF2202V)
R33  SIZECODESMD: 1608  VALUE4: (F)  VAL1: 0.047(F)  (hidden comment: WSLP0603R0470FEA)
R34  SIZECODESMD: 1608  VALUE4: (F)  VAL1: 10k(F)  (hidden comment: ERJ3EKF1002V)
R154  SIZECODESMD: 1608  VAL1: 0  (hidden comment: ERJ3GEY0R00V)
R155  SIZECODESMD: 2012  VAL1: 470(J)  (hidden comment: ERJP06J471V)
R197  SIZECODESMD: 1608  VALUE4: (F)  VAL1: 220(F)  (hidden comment: ERJ3EKF2200V)
R208  SIZECODESMD: 1608  VALUE4: (F)  VAL1: 10k(F)  (hidden comment: ERJ3EKF1002V)
R300  SIZECODESMD: 1608  VALUE4: (F)  VAL1: 1k(F)  NOTMOUNT: NOT MOUNT  (hidden comment: ERJ3EKF1001V)
R301  SIZECODESMD: 1608  VALUE4: (F)  VAL1: 10k(F)  (hidden comment: ERJ3EKF1002V)
R302  SIZECODESMD: 1608  VALUE4: (F)  VAL1: 10k(F)  NOTMOUNT: NOT MOUNT  (hidden comment: ERJ3EKF1002V)
R303  SIZECODESMD: 1608  VALUE4: (F)  VAL1: 10k(F)  (hidden comment: ERJ3EKF1002V)
R304  SIZECODESMD: 1608  VALUE4: (F)  VAL1: 10k(F)  NOTMOUNT: NOT MOUNT  (hidden comment: ERJ3EKF1002V)
R305  SIZECODESMD: 1608  VALUE4: (F)  VAL1: 10k(F)  (hidden comment: ERJ3EKF1002V)
R306  SIZECODESMD: 1608  VALUE4: (F)  VAL1: 10k(F)  NOTMOUNT: NOT MOUNT  (hidden comment: ERJ3EKF1002V)
R307  SIZECODESMD: 1608  VALUE4: (F)  VAL1: 10k(F)  (hidden comment: ERJ3EKF1002V)
R308  SIZECODESMD: 1608  VALUE4: (F)  VAL1: 10k(F)  NOTMOUNT: NOT MOUNT  (hidden comment: ERJ3EKF1002V)
T2  VAL2: Np:Ns1:Ns2:Ns3:Ns4:Naux=2.2:2:2:2:2:1  (hidden comment: 750342424)
TP5  TP  (value not drawn)
U?#2  DATE: 2023/03/24  TITLE: Multi Level Inverter using MOSFET  REVISION: 01  SHEETNUMBER: 2/10  DRAWINGNUMBER: RD208-SCHEMATIC-01  FUNCTION: Power-DC15V 1:4 ISOLATED DCDC CONVERTER  (hidden comment: WAKU_DEF100)

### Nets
GND: C20.2 C21.2 C103.2 C129.2 C137.2 C138.2 IC3.2(GND) R31.2 R32.2 R33.2 R34.2 R197.2 R208.2 R300.2 R307.2 R308.2 T2.4 T2.8  [project net SIG200]
V_LH: C20.1 D11.K(CATHODE) R307.1 R308.1  [project net SIG235]
V_UH: C17.1 D7.K(CATHODE) R301.1 R302.1  [project net SIG119]
V_UL: C17.2 R301.2 R302.2 T2.15
V_VH: C18.1 D8.K(CATHODE) R303.1 R304.1
V_VL: C18.2 R303.2 R304.2 T2.12  [project net SIG445]
V_WH: C19.1 D9.K(CATHODE) R305.1 R306.1
V_WL: C19.2 R305.2 R306.2 T2.9
VP_15R0_INV_ISO: C137.1 C138.1 R155.1 T2.2 TP5.1
L3803_FB: IC3.3(Vfb) R29.2 R34.1  [also labelled L3803_SENSE]
L3803_NGATE: IC3.6(NGATE) R154.1
L3803_VCC: C129.1 IC3.5(Vcc) R155.2
N3161846: Q2.1(S1) Q2.2(S2) Q2.3(S3) R30.2 R33.1
N3164696: C22.1 IC3.1(Ith/RUN)
N3166714: C22.2 R32.1
N16080427: Q2.4(G) R154.2 R208.1
N16289804: C128.2 R197.1
TRANS2_AUX: D10.A(ANODE) T2.3
TRANS2_AUX_B: C21.1 D10.K(CATHODE) R28.1 R31.1 R300.1
TRANS2_PRI: C128.1 Q2.5(D1) Q2.6(D2) Q2.7(D3) Q2.8(D4) T2.1
TRANS2_SEC1: D7.A(ANODE) T2.16
TRANS2_SEC2: D8.A(ANODE) T2.13
TRANS2_SEC3: D9.A(ANODE) T2.10
TRANS2_SEC4: D11.A(ANODE) T2.7
NetC103_1: C103.1 IC3.4(SENSE) R30.1
NetR28_2: R28.2 R29.1

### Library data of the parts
C17 = GRM31CR71E106MA12K: MANUFACTURER: MURATA; ITEM: CAP Ceramic; TIME: 08:44:46; UPDATEUSER: t5459927; SAVECOUNT: 1; OriginalSymbolOrigin: (0,0); INSTANCENAME: INS3167698
C18 = GRM31CR71E106MA12K: MANUFACTURER: MURATA; ITEM: CAP Ceramic; TIME: 08:44:46; UPDATEUSER: t5459927; SAVECOUNT: 1; OriginalSymbolOrigin: (0,0); INSTANCENAME: INS3170101
C19 = GRM31CR71E106MA12K: MANUFACTURER: MURATA; ITEM: CAP Ceramic; TIME: 08:44:46; UPDATEUSER: t5459927; SAVECOUNT: 1; OriginalSymbolOrigin: (0,0); INSTANCENAME: INS3170299
C20 = GRM31CR71E106MA12K: MANUFACTURER: MURATA; ITEM: CAP Ceramic; TIME: 08:44:46; UPDATEUSER: t5459927; SAVECOUNT: 1; OriginalSymbolOrigin: (0,0); INSTANCENAME: INS3170601
C21 = GRM31CR71E106MA12K: MANUFACTURER: MURATA; ITEM: CAP Ceramic; TIME: 08:44:46; UPDATEUSER: t5459927; SAVECOUNT: 1; OriginalSymbolOrigin: (0,0); INSTANCENAME: INS3166051
C22 = GRM1885C1H103JA01J: MANUFACTURER: MURATA; ITEM: CAP Ceramic; TIME: 08:44:46; UPDATEUSER: t5459927; SAVECOUNT: 1; OriginalSymbolOrigin: (0,0); INSTANCENAME: INS3166637
C103 = GRM1885C1H103JA01J: MANUFACTURER: MURATA; ITEM: CAP Ceramic; TIME: 08:44:46; UPDATEUSER: t5459927; SAVECOUNT: 1; OriginalSymbolOrigin: (0,0); INSTANCENAME: INS16080669
C128 = 06031A151FAT2A: MANUFACTURER: AVX; ITEM: CAP Ceramic; TIME: 08:44:46; UPDATEUSER: t5459927; SAVECOUNT: 1; OriginalSymbolOrigin: (0,0); INSTANCENAME: INS16121206
C129 = GRM31CR71E106MA12K: MANUFACTURER: MURATA; ITEM: CAP Ceramic; TIME: 08:44:46; UPDATEUSER: t5459927; SAVECOUNT: 1; OriginalSymbolOrigin: (0,0); INSTANCENAME: INS16615608
C137 = GRM21BR61H475KE51L: MANUFACTURER: MURATA; ITEM: CAP Ceramic; TIME: 08:44:46; UPDATEUSER: t5459927; SAVECOUNT: 1; OriginalSymbolOrigin: (0,0); INSTANCENAME: INS17252024
C138 = GRM21BR61H475KE51L: MANUFACTURER: MURATA; ITEM: CAP Ceramic; TIME: 08:44:46; UPDATEUSER: t5459927; SAVECOUNT: 1; OriginalSymbolOrigin: (0,0); INSTANCENAME: INS17252038
D7 = CMS10_TE12L,Q,M_: MANUFACTURER: TOSHIBA; COMP: CMS10; ITEM: DIODE; TIME: 08:44:46; UPDATEUSER: t5459927; SAVECOUNT: 1; OriginalSymbolOrigin: (0,0); INSTANCENAME: INS3167754
D8 = CMS10_TE12L,Q,M_: MANUFACTURER: TOSHIBA; COMP: CMS10; ITEM: DIODE; TIME: 08:44:46; UPDATEUSER: t5459927; SAVECOUNT: 1; OriginalSymbolOrigin: (0,0); INSTANCENAME: INS3170061
D9 = CMS10_TE12L,Q,M_: MANUFACTURER: TOSHIBA; COMP: CMS10; ITEM: DIODE; TIME: 08:44:46; UPDATEUSER: t5459927; SAVECOUNT: 1; OriginalSymbolOrigin: (0,0); INSTANCENAME: INS3170259
D10 = CMS10_TE12L,Q,M_: COMP: CMS10; ITEM: DIODE; TIME: 08:44:46; UPDATEUSER: t5459927; SAVECOUNT: 1; OriginalSymbolOrigin: (0,0); INSTANCENAME: INS3165224
D11 = CMS10_TE12L,Q,M_: MANUFACTURER: TOSHIBA; COMP: CMS10; ITEM: DIODE; TIME: 08:44:46; UPDATEUSER: t5459927; SAVECOUNT: 1; OriginalSymbolOrigin: (0,0); INSTANCENAME: INS3170561
IC3 = LTC3803HS6_5#TRMPBF: MANUFACTURER: Analog Devices; ITEM: IC DCDC; VAL2: DCDC CONTROLLER; COMP: LTC3803HS6-5_TRMPBF; TIME: 08:44:46; UPDATEUSER: PS4_common_PC; UPDATETIME: 15:55:48; SAVECOUNT: 3; SAVEAREA0: -42732,-39864,65274,9349; OriginalSymbolOrigin: (0,0)
Q2 = TPN7R006PL,L1Q: ITEM: FET; COMP: TPN7R006PL_L1Q; ORDER: 0; TIME: 08:44:46; UPDATEUSER: t5459927; SAVECOUNT: 1; OriginalSymbolOrigin: (0,0); INSTANCENAME: INS3164116
R28 = ERJ3EKF3302V: MANUFACTURER: Panasonic; ITEM: Register; VAL2: 100mW; TIME: 08:44:46; UPDATEUSER: t5459927; SAVECOUNT: 1; OriginalSymbolOrigin: (0,0); INSTANCENAME: INS15947925
R29 = ERJ3EKF5102V: MANUFACTURER: Panasonic; ITEM: Register; VAL2: 100mW; TIME: 08:44:46; UPDATEUSER: t5459927; SAVECOUNT: 1; OriginalSymbolOrigin: (0,0); INSTANCENAME: INS15947972
R30 = ERJ3EKF4701V: MANUFACTURER: Panasonic; ITEM: Register; VAL2: 100mW; TIME: 08:44:46; UPDATEUSER: t5459927; SAVECOUNT: 1; OriginalSymbolOrigin: (0,0); INSTANCENAME: INS15947636
R31 = ERJ3EKF1001V: MANUFACTURER: Panasonic; ITEM: Register; VAL2: 100mW; TIME: 08:44:46; UPDATEUSER: t5459927; SAVECOUNT: 1; OriginalSymbolOrigin: (0,0); INSTANCENAME: INS15954881
R32 = ERJ3EKF2202V: MANUFACTURER: Panasonic; ITEM: Register; VAL2: 100mW; TIME: 08:44:46; UPDATEUSER: t5459927; SAVECOUNT: 1; OriginalSymbolOrigin: (0,0); INSTANCENAME: INS16644073
R33 = WSLP0603R0470FEA: MANUFACTURER: Vishay; ITEM: Register; VAL2: 400mW; TIME: 08:44:47; UPDATEUSER: t5459927; SAVECOUNT: 1; OriginalSymbolOrigin: (0,0); INSTANCENAME: INS15955052
R34 = ERJ3EKF1002V: MANUFACTURER: Panasonic; ITEM: Register; VAL2: 100mW; TIME: 08:44:46; UPDATEUSER: t5459927; SAVECOUNT: 1; OriginalSymbolOrigin: (0,0); INSTANCENAME: INS15947827
R154 = ERJ3GEY0R00V: MANUFACTURER: Panasonic; ITEM: Register; VAL2: 1/10W; TIME: 08:44:45; UPDATEUSER: t5459927; SAVECOUNT: 1; OriginalSymbolOrigin: (0,0); INSTANCENAME: INS16643171
R155 = ERJP06J471V: MANUFACTURER: Panasonic; ITEM: Register; VAL2: 500mW; VALUE4: (J); TIME: 08:44:46; UPDATEUSER: t5459927; SAVECOUNT: 1; OriginalSymbolOrigin: (0,0); INSTANCENAME: INS16122030
R197 = ERJ3EKF2200V: MANUFACTURER: Panasonic; ITEM: Register; VAL2: 100mW; TIME: 08:44:46; UPDATEUSER: t5459927; SAVECOUNT: 1; OriginalSymbolOrigin: (0,0); INSTANCENAME: INS16121237
R208 = ERJ3EKF1002V: MANUFACTURER: Panasonic; ITEM: Register; VAL2: 100mW; TIME: 08:44:46; UPDATEUSER: t5459927; SAVECOUNT: 1; OriginalSymbolOrigin: (0,0); INSTANCENAME: INS16643191
R300 = ERJ3EKF1001V: MANUFACTURER: Panasonic; ITEM: Register; VAL2: 100mW; TIME: 08:44:46; UPDATEUSER: t5459927; SAVECOUNT: 1; OriginalSymbolOrigin: (0,0); INSTANCENAME: INS17177028
R301 = ERJ3EKF1002V: MANUFACTURER: Panasonic; ITEM: Register; VAL2: 100mW; TIME: 08:44:46; UPDATEUSER: t5459927; SAVECOUNT: 1; OriginalSymbolOrigin: (0,0); INSTANCENAME: INS17199274
R302 = ERJ3EKF1002V: MANUFACTURER: Panasonic; ITEM: Register; VAL2: 100mW; TIME: 08:44:46; UPDATEUSER: t5459927; SAVECOUNT: 1; OriginalSymbolOrigin: (0,0); INSTANCENAME: INS17199242
R303 = ERJ3EKF1002V: MANUFACTURER: Panasonic; ITEM: Register; VAL2: 100mW; TIME: 08:44:46; UPDATEUSER: t5459927; SAVECOUNT: 1; OriginalSymbolOrigin: (0,0); INSTANCENAME: INS17198846
R304 = ERJ3EKF1002V: MANUFACTURER: Panasonic; ITEM: Register; VAL2: 100mW; TIME: 08:44:46; UPDATEUSER: t5459927; SAVECOUNT: 1; OriginalSymbolOrigin: (0,0); INSTANCENAME: INS17199336
R305 = ERJ3EKF1002V: MANUFACTURER: Panasonic; ITEM: Register; VAL2: 100mW; TIME: 08:44:46; UPDATEUSER: t5459927; SAVECOUNT: 1; OriginalSymbolOrigin: (0,0); INSTANCENAME: INS17198902
R306 = ERJ3EKF1002V: MANUFACTURER: Panasonic; ITEM: Register; VAL2: 100mW; TIME: 08:44:46; UPDATEUSER: t5459927; SAVECOUNT: 1; OriginalSymbolOrigin: (0,0); INSTANCENAME: INS17199378
R307 = ERJ3EKF1002V: MANUFACTURER: Panasonic; ITEM: Register; VAL2: 100mW; TIME: 08:44:46; UPDATEUSER: t5459927; SAVECOUNT: 1; OriginalSymbolOrigin: (0,0); INSTANCENAME: INS17198958
R308 = ERJ3EKF1002V: MANUFACTURER: Panasonic; ITEM: Register; VAL2: 100mW; TIME: 08:44:46; UPDATEUSER: t5459927; SAVECOUNT: 1; OriginalSymbolOrigin: (0,0); INSTANCENAME: INS17199357
T2 = 750342424: MANUFACTURER: WURTH; ITEM: Transformer; TIME: 08:44:46; UPDATEUSER: t5459927; SAVECOUNT: 1; OriginalSymbolOrigin: (0,2540); INSTANCENAME: INS3163135
TP5 = TP: as TP1 on sheet 1
U?#2 = WAKU_DEF100: PLOTTIME: HH:MM; SAVEAREA0: 185750,-43960,448537,75779; TIME: 14:30:25; UPDATEUSER: PS4_common_PC; UPDATETIME: 08:23:32; SAVECOUNT: 8; OriginalSymbolOrigin: (10160,284480)

## Sheet 3.SchDoc
size 420 x 297 mm
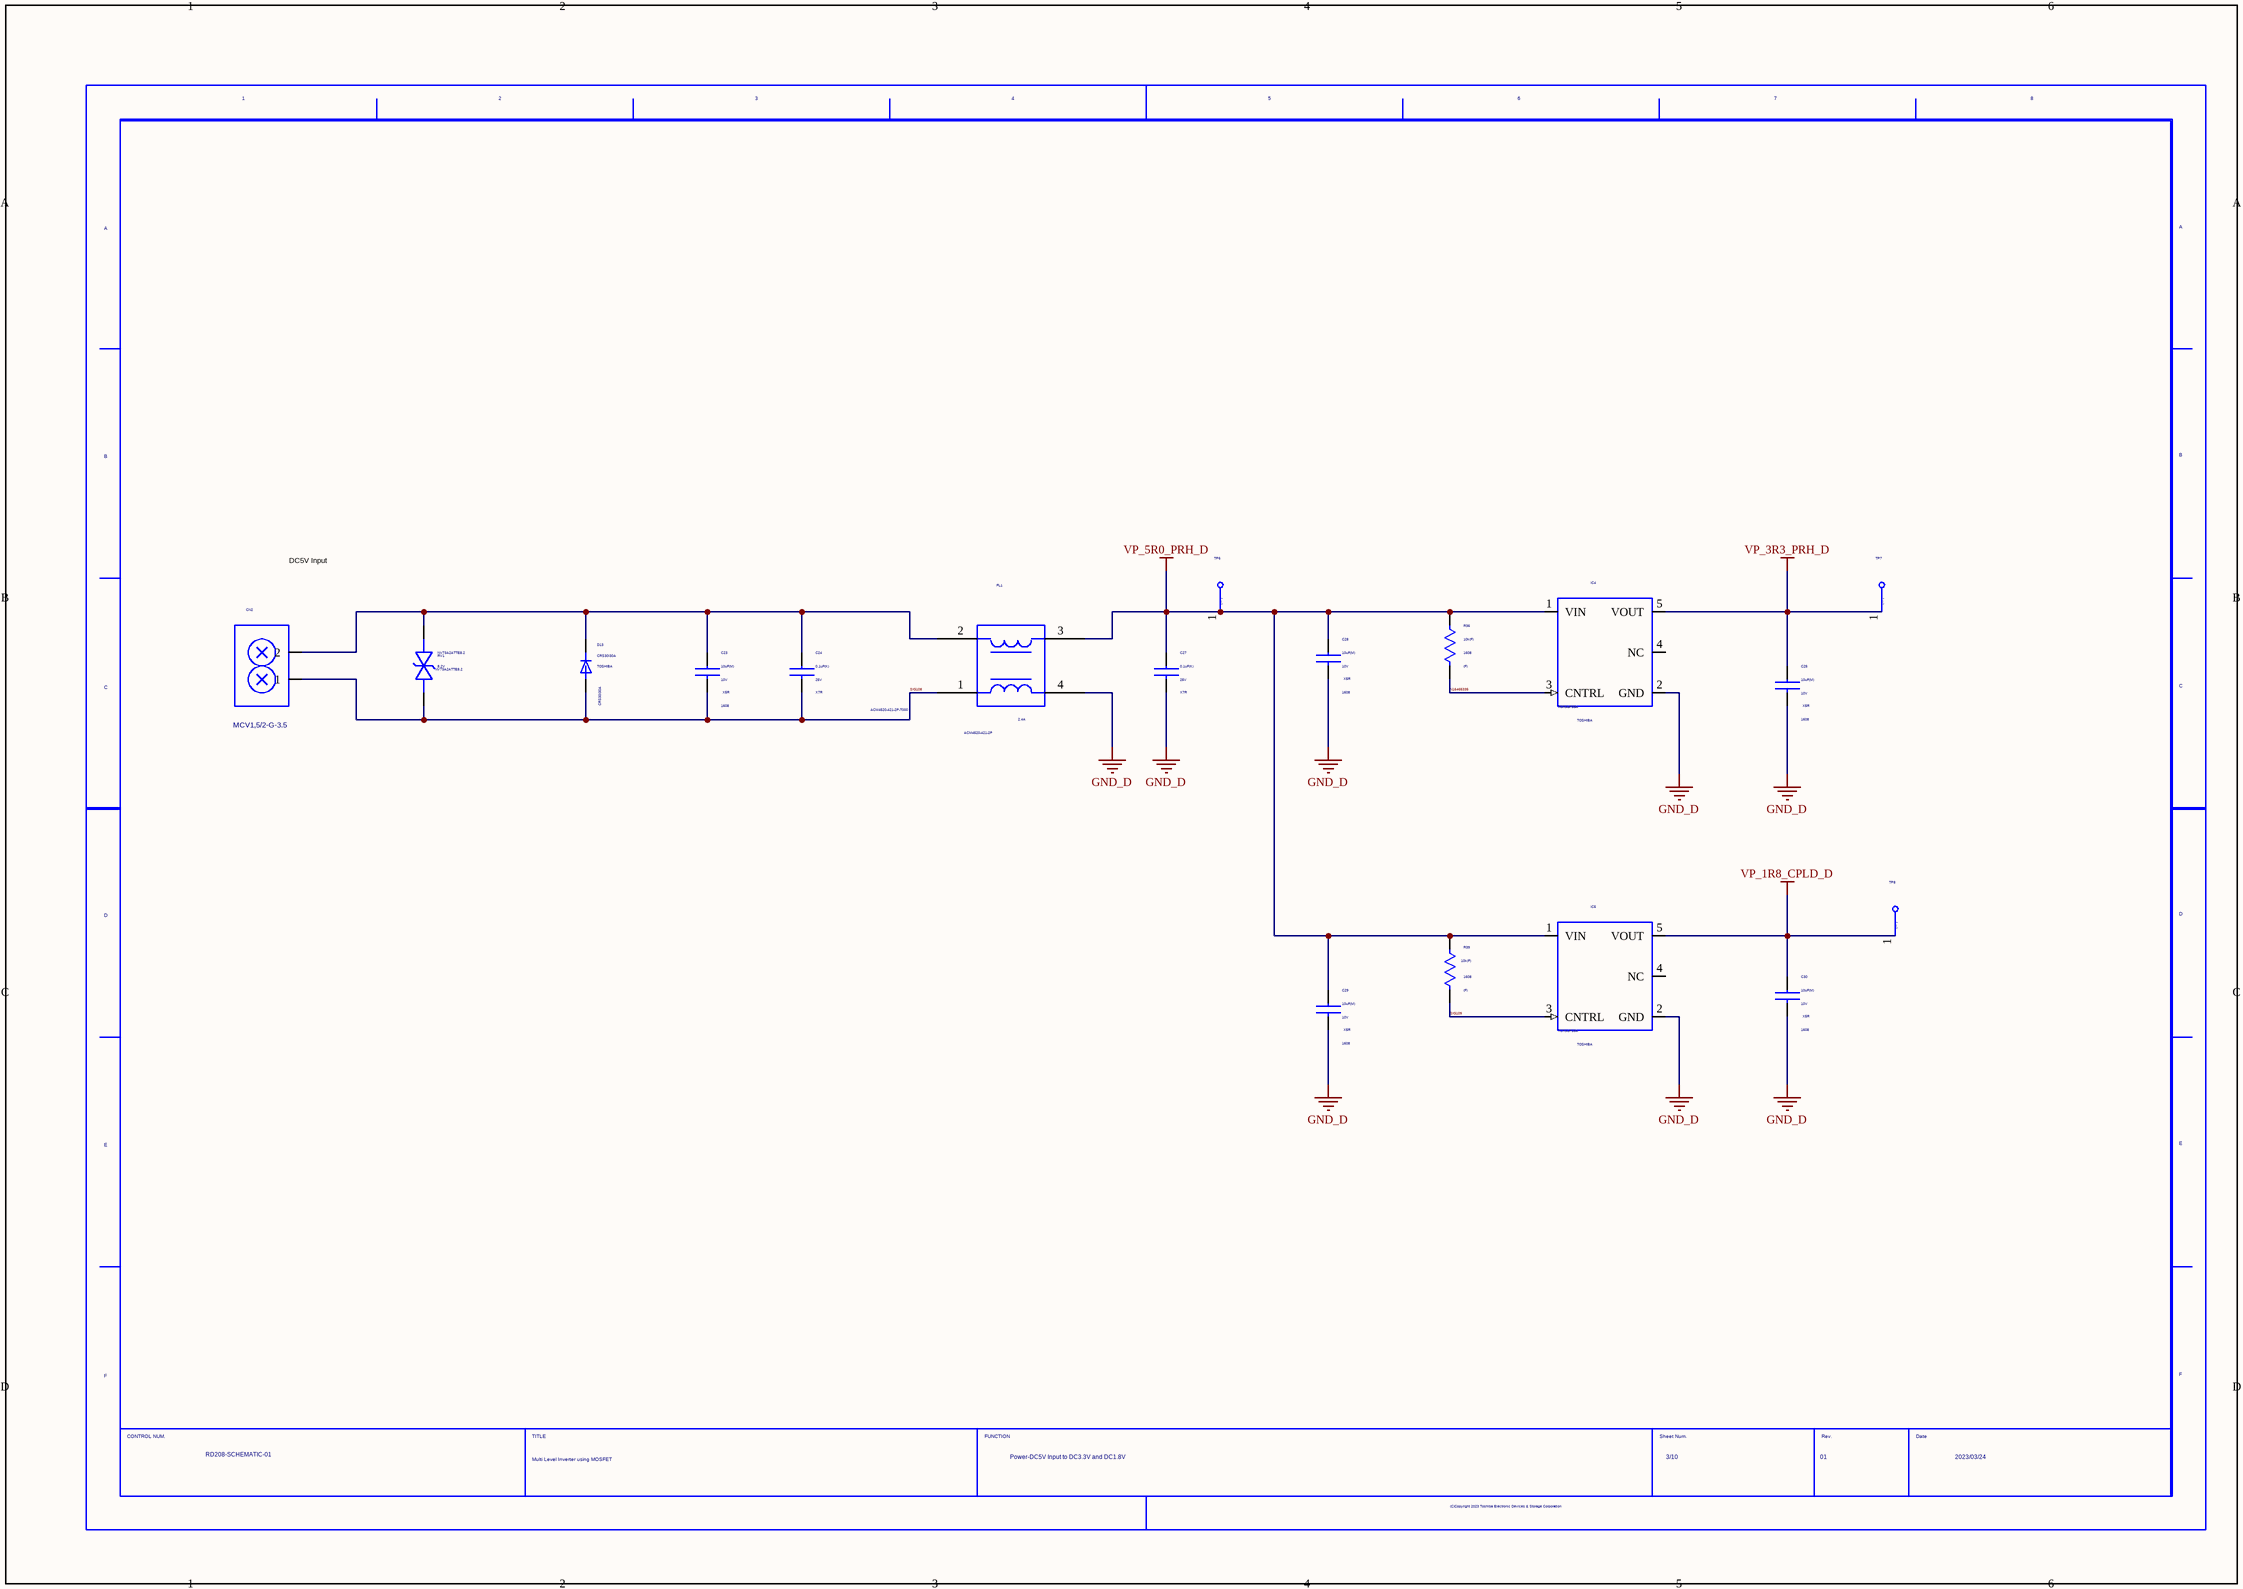
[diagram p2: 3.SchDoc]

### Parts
(Parts that share a designator on the sheet are numbered #1, #2 ... from top to bottom, then left to right.)
C23  VAL2: 10V  SIZECODESMD: 1608  VALUE4: X5R  VAL1: 10uF(M)  (hidden comment: GRM188R61A106ME69D)
C24  VAL2: 25V  VALUE4: X7R  VAL1: 0.1uF(K)  (hidden comment: GRM155R71E104KE14D)
C25  VAL2: 10V  SIZECODESMD: 1608  VALUE4: X5R  VAL1: 10uF(M)  (hidden comment: GRM188R61A106ME69D)
C27  VAL2: 25V  VALUE4: X7R  VAL1: 0.1uF(K)  (hidden comment: GRM155R71E104KE14D)
C28  VAL2: 10V  SIZECODESMD: 1608  VALUE4: X5R  VAL1: 10uF(M)  (hidden comment: GRM188R61A106ME69D)
C29  VAL2: 10V  SIZECODESMD: 1608  VALUE4: X5R  VAL1: 10uF(M)  (hidden comment: GRM188R61A106ME69D)
C30  VAL2: 10V  SIZECODESMD: 1608  VALUE4: X5R  VAL1: 10uF(M)  (hidden comment: GRM188R61A106ME69D)
CN2  SCH_NAME: MCV1,5/2-G-3.5  (hidden comment: 1843606)
D13  USERCOMPTEXT3: TOSHIBA  (hidden comment: CRS30I30A)
FL1  VAL2: 2.4A  VAL1: ACM4520-421-2P-T000  SCH_NAME: ACM4520-421-2P  (hidden comment: ACM4520_421_2P_T000)
IC4  USERCOMPTEXT3: TOSHIBA  (hidden comment: TCR3UF33A)
IC5  USERCOMPTEXT3: TOSHIBA  VAL3: TCR3UF18A  (hidden comment: TCR3UF33A)
R36  SIZECODESMD: 1608  VALUE4: (F)  VAL1: 10k(F)  (hidden comment: ERJ3EKF1002V)
R39  SIZECODESMD: 1608  VALUE4: (F)  VAL1: 10k(F)  (hidden comment: ERJ3EKF1002V)
RV1  VAL2: 8.2V  VAL1: NV73A2ATTE8.2  (hidden comment: NV73A2ATTE8_2)
TP6  TP  (value not drawn)
TP7  TP  (value not drawn)
TP8  TP  (value not drawn)
U?#3  DATE: 2023/03/24  TITLE: Multi Level Inverter using MOSFET  DRAWINGNUMBER: RD208-SCHEMATIC-01  REVISION: 01  SHEETNUMBER: 3/10  FUNCTION: Power-DC5V Input to DC3.3V and DC1.8V  (hidden comment: WAKU_DEF100)

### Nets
GND_D: C25.2 C27.2 C28.2 C29.2 C30.2 FL1.4(CG4) IC4.2(GND) IC5.2(GND)  [project net SIG10]
VP_1R8_CPLD_D: C30.1 IC5.5(VOUT) TP8.1  [project net SIG501]
VP_3R3_PRH_D: C25.1 IC4.5(VOUT) TP7.1  [project net SIG107]
VP_5R0_PRH_D: C27.1 C28.1 C29.1 FL1.3(PSG) IC4.1(VIN) IC5.1(VIN) R36.1 R39.1 TP6.1  [project net SIG104]
5V_IN: C23.1 C24.1 CN2.2 D13.K(CATHODE) FL1.2(CB) RV1.2(C)
N16465335: IC4.3(CNTRL) R36.2
SIG108: C23.2 C24.2 CN2.1 D13.A(ANODE) FL1.1(B) RV1.1(A)
SIG109: IC5.3(CNTRL) R39.2

Not connected (* = marked no-connect by the designer): IC4 4(NC); IC5 4(NC)

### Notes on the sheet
- DC5V Input

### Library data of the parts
C23 = GRM188R61A106ME69D: MANUFACTURER: MURATA; ITEM: CAP Ceramic; TIME: 08:44:46; UPDATEUSER: t5459927; SAVECOUNT: 1; OriginalSymbolOrigin: (0,0); INSTANCENAME: INS16466301
C24 = GRM155R71E104KE14D: MANUFACTURER: MURATA; ITEM: CAP Ceramic; SIZECODESMD: 1005; TIME: 08:44:45; UPDATEUSER: t5459927; SAVECOUNT: 1; OriginalSymbolOrigin: (0,0); INSTANCENAME: INS16466561
C25 = GRM188R61A106ME69D: MANUFACTURER: MURATA; ITEM: CAP Ceramic; TIME: 08:44:46; UPDATEUSER: t5459927; SAVECOUNT: 1; OriginalSymbolOrigin: (0,0); INSTANCENAME: INS16465857
C27 = GRM155R71E104KE14D: MANUFACTURER: MURATA; ITEM: CAP Ceramic; SIZECODESMD: 1005; TIME: 08:44:45; UPDATEUSER: t5459927; SAVECOUNT: 1; OriginalSymbolOrigin: (0,0); INSTANCENAME: INS16466055
C28 = GRM188R61A106ME69D: MANUFACTURER: MURATA; ITEM: CAP Ceramic; TIME: 08:44:46; UPDATEUSER: t5459927; SAVECOUNT: 1; OriginalSymbolOrigin: (0,0); INSTANCENAME: INS16466267
C29 = GRM188R61A106ME69D: MANUFACTURER: MURATA; ITEM: CAP Ceramic; TIME: 08:44:46; UPDATEUSER: t5459927; SAVECOUNT: 1; OriginalSymbolOrigin: (0,0); INSTANCENAME: INS16465891
C30 = GRM188R61A106ME69D: MANUFACTURER: MURATA; ITEM: CAP Ceramic; TIME: 08:44:46; UPDATEUSER: t5459927; SAVECOUNT: 1; OriginalSymbolOrigin: (0,0); INSTANCENAME: INS16466167
CN2 = 1843606: MANUFACTURER: PHOENIX CONTACT; ITEM: Connector 2Pin Terminal Block; TIME: 08:44:48; UPDATEUSER: t5459927; SAVECOUNT: 1; SAVEAREA0: -7641,-15544,14757,852; OriginalSymbolOrigin: (0,0); INSTANCENAME: INS16809162
D13 = CRS30I30A: ITEM: DIODE; TIME: 08:44:48; UPDATEUSER: t5459927; SAVECOUNT: 1; OriginalSymbolOrigin: (0,0); INSTANCENAME: INS17152863
FL1 = ACM4520_421_2P_T000: MANUFACTURER: TDK; ITEM: Filter; TIME: 08:44:48; UPDATEUSER: t5459927; SAVECOUNT: 1; SAVEAREA0: -11402,-15649,23384,1144; OriginalSymbolOrigin: (0,0); INSTANCENAME: INS16465959
IC4 IC5 = TCR3UF33A: ITEM: IC LDO; VAL2: LDO; TIME: 08:44:48; UPDATEUSER: PS4_common_PC; UPDATETIME: 15:57:17; SAVECOUNT: 3; SAVEAREA0: -27364,-26218,44601,6573; OriginalSymbolOrigin: (0,0)
R36 = ERJ3EKF1002V: MANUFACTURER: Panasonic; ITEM: Register; VAL2: 100mW; TIME: 08:44:46; UPDATEUSER: t5459927; SAVECOUNT: 1; OriginalSymbolOrigin: (0,0); INSTANCENAME: INS16466335
R39 = ERJ3EKF1002V: MANUFACTURER: Panasonic; ITEM: Register; VAL2: 100mW; TIME: 08:44:46; UPDATEUSER: t5459927; SAVECOUNT: 1; OriginalSymbolOrigin: (0,0); INSTANCENAME: INS16465707
RV1 = NV73A2ATTE8_2: MANUFACTURER: KOA; ITEM: Varistor 8.2V; SIZECODESMD: 2012; TIME: 08:44:47; UPDATEUSER: t5459927; SAVECOUNT: 1; OriginalSymbolOrigin: (0,0); INSTANCENAME: INS16465533
TP6-TP8 = TP: as TP1 on sheet 1
U?#3 = WAKU_DEF100: PLOTTIME: HH:MM; SAVEAREA0: 185750,-43960,448537,75779; TIME: 14:30:25; UPDATEUSER: PS4_common_PC; UPDATETIME: 08:24:18; SAVECOUNT: 8; OriginalSymbolOrigin: (10160,284480)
